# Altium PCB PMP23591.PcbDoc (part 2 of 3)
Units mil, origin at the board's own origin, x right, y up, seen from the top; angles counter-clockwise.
Board outline 3937.01 x 3937.01 mil, 6 copper layers (Top Layer, GND, Power Layer, Signal Layer, GND (Mid4), Bottom Layer), stack 66.824 mil thick; 197 components, 79 nets, 496 pads, 588 vias.
Unrouted connection lines stored in the file: 309.
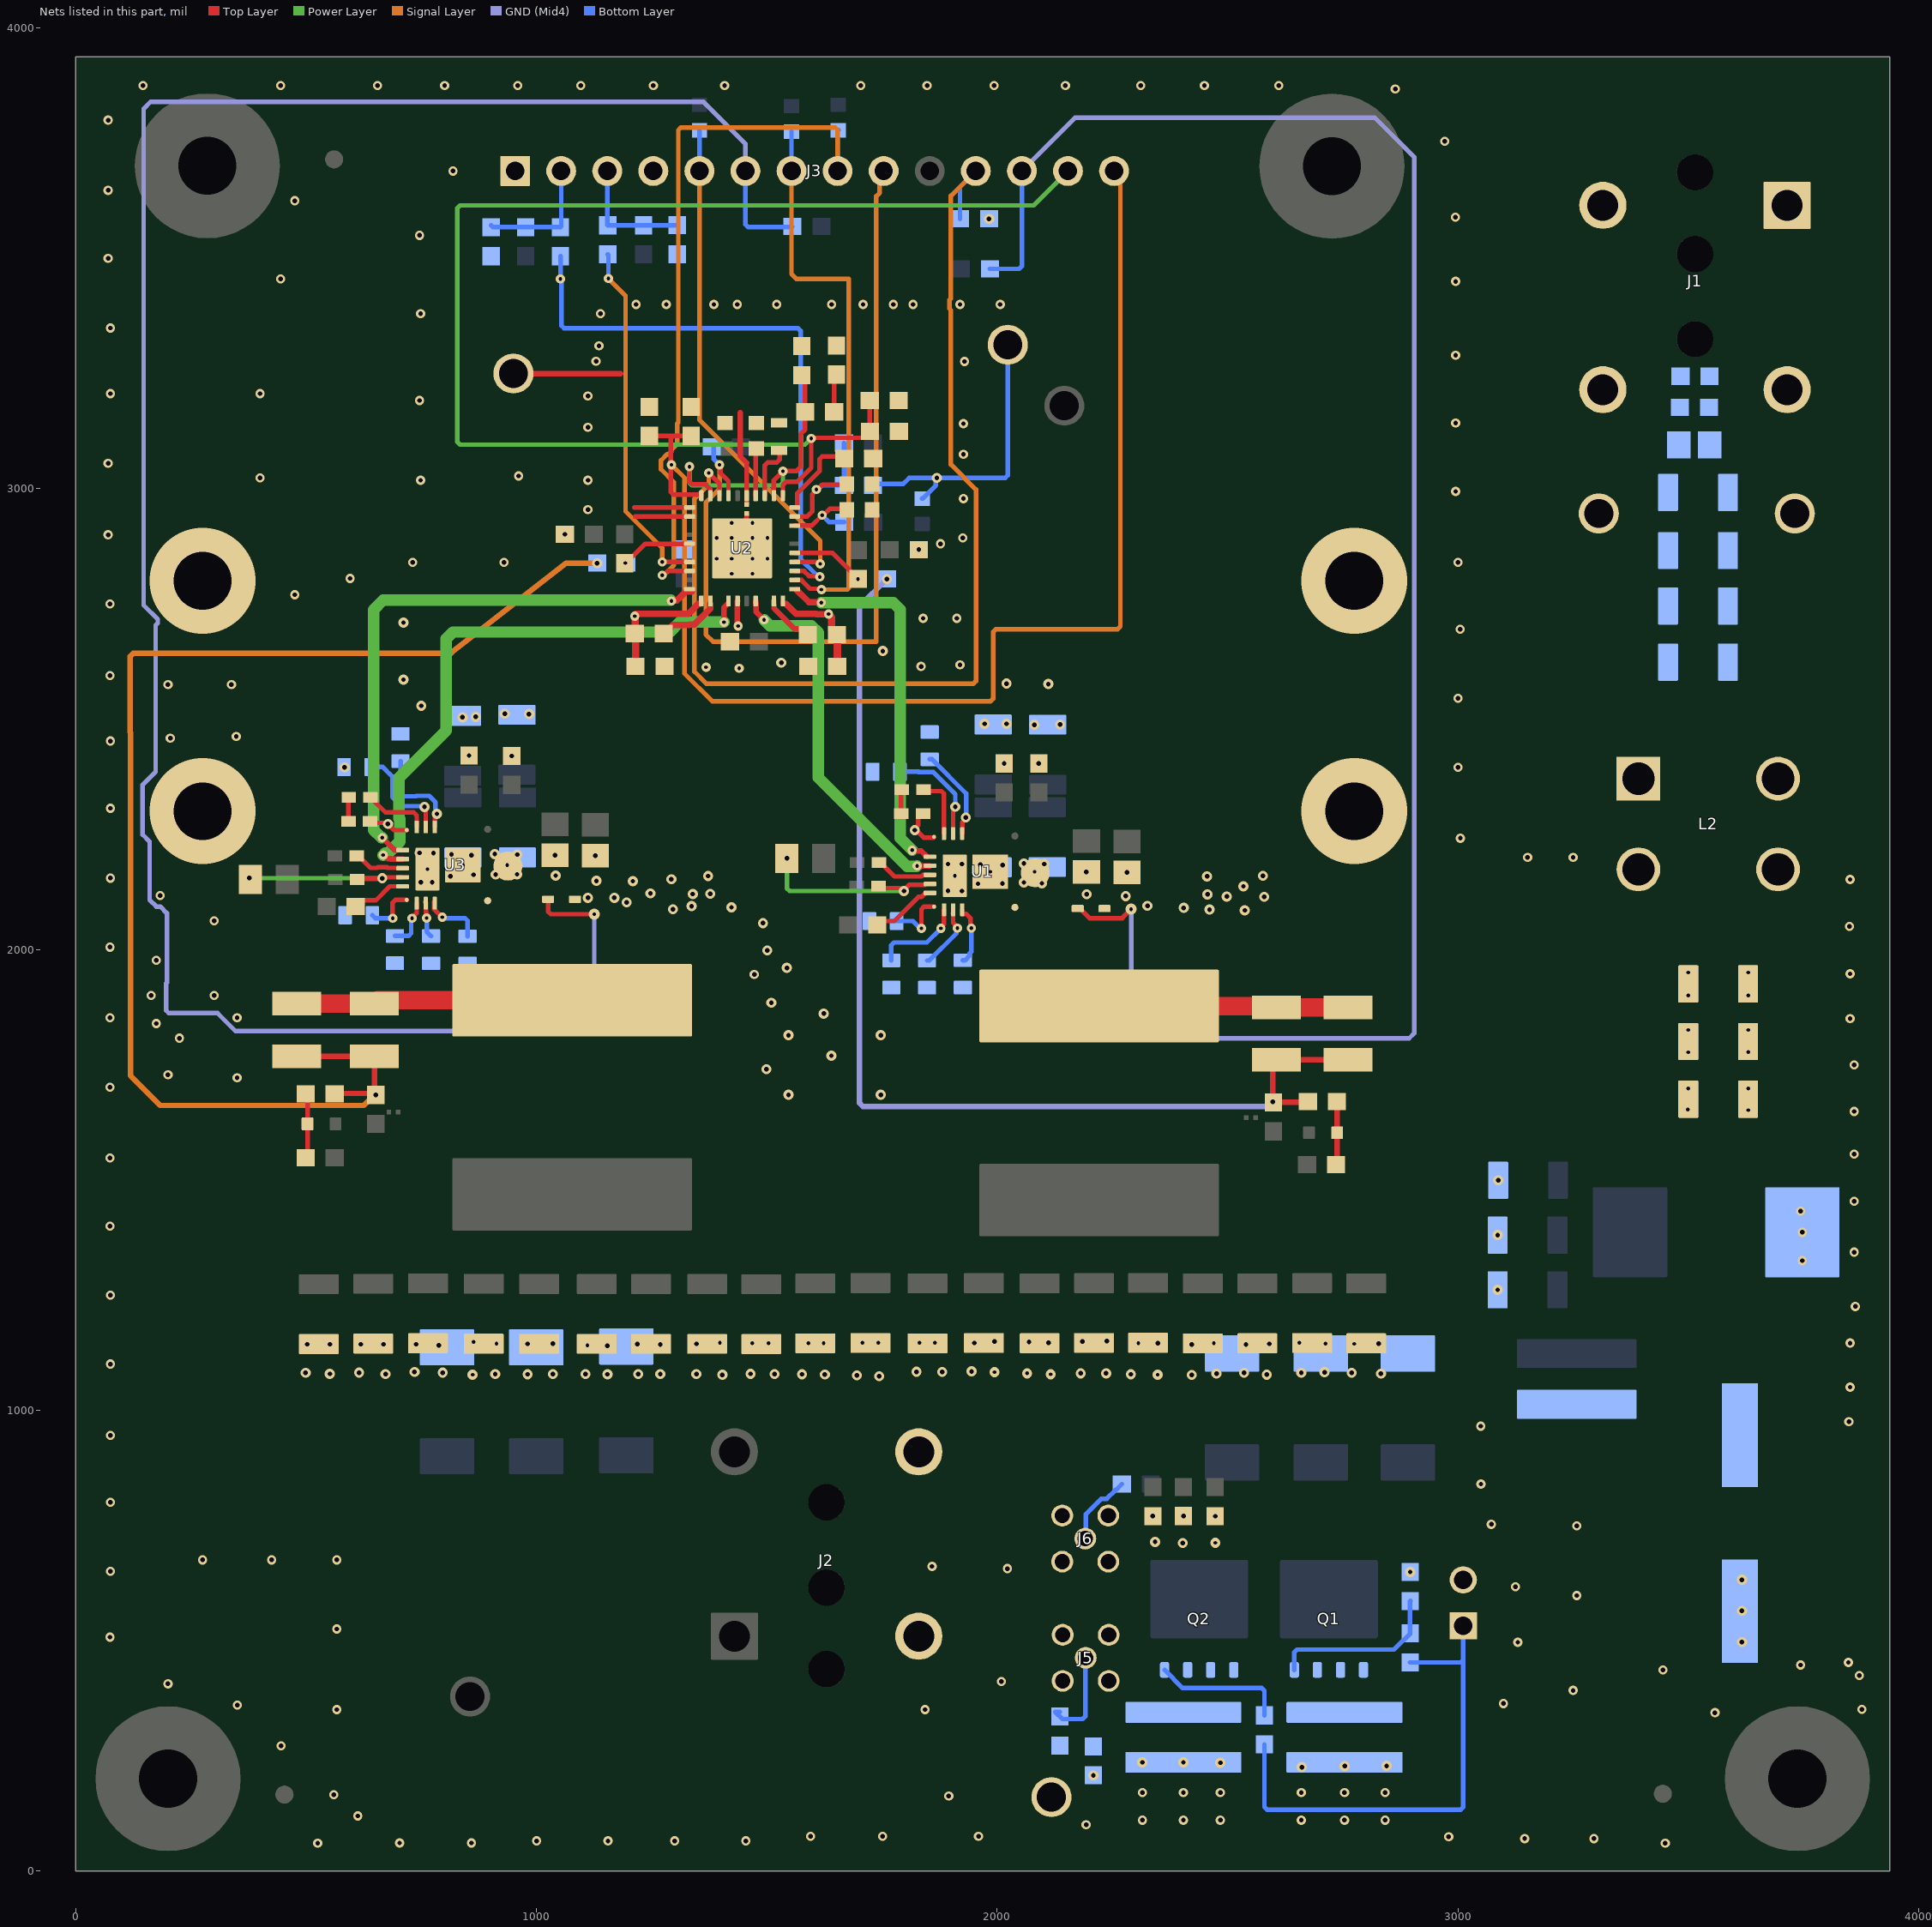
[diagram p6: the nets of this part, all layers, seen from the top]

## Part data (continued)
C2 C57: library part CMP-0007081-4, "CAP, CERM, 1000 pF, 100 V, +/- 10%, X7R, AEC-Q200 Grade 1, 0603", Cap_Case=0603, Manufacturer=TDK, Supplier Part Number 1=445-5806-1-ND, TempCo=X7R, Tolerance_%=10%, Value1="1.97137 ohm", Value2=100V, ValueDisplayed=1000pF
C3 C58: library part CMP-0007468-5, "CAP, CERM, 0.01 uF, 100 V, +/- 10%, X7R, 0603", Cap_Case=0603, Manufacturer=MuRata, Supplier Part Number 1=GRM188R72A103KA01D-ND, TempCo=X7R, Tolerance_%=10%, Value1=Unknown, Value2=100V, ValueDisplayed=0.01uF
C4: library part CMP-0007722-2, "CAP, CERM, 0.1 uF, 100 V, +/- 10%, X7R, 0805", Cap_Case=0805, Manufacturer=Kemet, Supplier Part Number 1=399-3486-1-ND, TempCo=X7R, Tolerance_%=10%, Value1="0.064 ohm", Value2=100V, ValueDisplayed=0.1uF
C5 C6 C7 C8 C9 C10 C11 C12 C13 C14 C15 C16 C17 C18 C19 C20 C21 C45 C46 C47 C48: library part CMP-0093675-1, "4.7uF ±10% 100V Ceramic Capacitor X7S 1210 (3225 Metric)", Manufacturer=Murata, Operating Temperature Range="-55°C to +125°C", TempCo=22%, Temperature Characteristic=X7S, Tolerance_%=10%, ValueDisplayed=4.7uF
C22 C53: library part CMP-0008013-2, "CAP, CERM, 4.7 uF, 25 V, +/- 10%, X7S, AEC-Q200 Grade 1, 0805", Cap_Case=0805, Manufacturer=MuRata, Supplier Part Number 1=81-GCM21BC71E475KE6L, TempCo=X7S, Tolerance_%=10%, Value1=Unknown, Value2=25V, ValueDisplayed=4.7uF
C23 C28 C54 C56: library part CMP-0080702-1, "CAP, CERM, 0.1 µF, 16 V,+/- 5%, X7R, AEC-Q200 Grade 1, 0402", Cap_Case=0402, Manufacturer=MuRata, Supplier Part Number 1=490-16433-1-ND, TempCo=X7R, Tolerance_%=5%, Value2=16V, ValueDisplayed=0.1µF
C24 C25 C38 C42 C44 C49 C50 C55 C59 C75 C77 C78: library part CMP-0007077-5, "CAP, CERM, 0.1 uF, 25 V, +/- 10%, X7R, AEC-Q200 Grade 1, 0603", Cap_Case=0603, Manufacturer=TDK, Supplier Part Number 1=445-5667-1-ND, TempCo=X7R, Tolerance_%=10%, Value1=Unknown, Value2=25V, ValueDisplayed=0.1uF
C26 C27 C51 C52: library part CMP-0007996-2, "CAP, CERM, 0.22 uF, 100 V, +/- 10%, X7R, 0805", Cap_Case=0805, Manufacturer="Samsung Electro-Mechanics", TempCo=X7R, Tolerance_%=10%, Value1=Unknown, Value2=100V, ValueDisplayed=0.22uF
C29 C30 C31 C32 C33 C60 C61 C62 C63 C64 C72 C73 C74 C76 C79 C80 C81 C82 C83 C84: library part CMP-0036912-1, "Cap Ceramic 22uF 25V X7R 20% Pad SMD 1210 +125°C Automotive T/R", Manufacturer=TDK, Operating Temperature Range="-55°C to +125°C", TempCo=15%, Temperature Characteristic=X7R, Tolerance_%=0.2%, ValueDisplayed=22uF
C34: library part CMP-0092618-1, "Cap Tant Polymer 220uF 16VDC E CASE 20% (7.3 X 4.3 X 4.1mm) SMD 7343-43 0.025 Ohm 125C T/R", Digikey Part Number=478-TCME227M016R0025ECT-ND, Leakage Current=352uA, Manufacturer=AVX, Mouser Part Number=581-TCME227M016R025E, Operating Temperature Range="-55°C to +125°C", Tolerance_%=20%, ValueDisplayed=220uF
C35 C36 C65 C66 C67: library part CMP-0124500-1, "Cap Tant Polymer 150uF 16VDC E CASE 20%( 7.3 X 4.3 X 4.1mm) J Lead SMD 7343-43 0.025 Ohm 125C T/R", Digikey Part Number=478-TCQE157M016R0025ECT-ND, Leakage Current=240uA, Manufacturer="KYOCERA AVX", Mouser Part Number=581-TCQE157M016R25E, Operating Temperature Range="-55°C to +125°C", Tolerance_%=20%, ValueDisplayed=150uF
C37 C68: library part CMP-0007508-5, "CAP, CERM, 1 uF, 50 V, +/- 10%, X7R, 0603", Cap_Case=0603, Manufacturer="Taiyo Yuden", Supplier Part Number 1=587-3247-1-ND, TempCo=X7R, Tolerance_%=10%, Value1=Unknown, Value2=50V, ValueDisplayed=1uF
C39: library part CMP-0007469-4, "CAP, CERM, 0.1 uF, 100 V, +/- 10%, X7R, 0603", Cap_Case=0603, Manufacturer=MuRata, Supplier Part Number 1=490-3285-1-ND, TempCo=X7R, Tolerance_%=10%, Value1=Unknown, Value2=100V, ValueDisplayed=0.1uF
C40: library part CMP-0064936-4, "CAP, CERM, 4.7 uF, 16 V,+/- 10%, X7R, 0603", Cap_Case=0603, Manufacturer=MuRata, TempCo=X7R, Tolerance_%=10%, Value1=Unknown, Value2=16V, ValueDisplayed=4.7uF
C41: library part CMP-0079154-1, "CAP, CERM, 1 µF, 16 V,+/- 10%, X7R, AEC-Q200 Grade 1, 0603", Cap_Case=0603, Manufacturer=MuRata, Supplier Part Number 1=490-12657-1-ND, TempCo=X7R, Tolerance_%=10%, Value2=16V, ValueDisplayed=1µF
C43 C69: library part CMP-0007130-4, "CAP, CERM, 100 pF, 100 V, +/- 5%, C0G/NP0, AEC-Q200 Grade 1, 0603", Cap_Case=0603, Manufacturer=MuRata, Supplier Part Number 1=490-4771-1-ND, TempCo=C0G/NP0, Tolerance_%=5%, Value1=Unknown, Value2=100V, ValueDisplayed=100pF
C70: library part CMP-0007069-4, "CAP, CERM, 10 pF, 50 V, +/- 5%, C0G/NP0, AEC-Q200 Grade 1, 0603", Cap_Case=0603, Manufacturer=TDK, Supplier Part Number 1=445-5628-1-ND, TempCo=C0G/NP0, Tolerance_%=5%, Value1=Unknown, Value2=50V, ValueDisplayed=10pF
C71: library part CMP-0007143-4, "CAP, CERM, 0.01 uF, 50 V, +/- 10%, X7R, AEC-Q200 Grade 1, 0603", Cap_Case=0603, Manufacturer=MuRata, Supplier Part Number 1=490-4778-1-ND, TempCo=X7R, Tolerance_%=10%, Value1=Unknown, Value2=50V, ValueDisplayed=0.01uF
"CAUTION HOT SURFACE1": library part CMP-0074837-2, "IEC 61010-1 Hot Surface Warning", Manufacturer="Texas Instruments"
FID1 FID2 FID3: library part CMP-0077181-1, "Fiducial mark.  There is nothing to buy or mount.", Manufacturer=N/A
GND1 PGND1: library part CMP-0055148-1, "Test Point, Multipurpose, Black, TH", Color=Black, Manufacturer=Keystone, PartNumber=5011, Supplier Part Number 1=36-5011-ND
H1 H2 H3 H4: library part CMP-0003617-1, "Machine Screw, Round, #4-40 x 1/4, Nylon, Philips panhead", Manufacturer="B&F Fastener Supply", Supplier Part Number 1=H542-ND
H5 H6 H7 H8: library part CMP-0003610-1, "Standoff, Hex, 0.5\"L #4-40 Nylon", Manufacturer=Keystone, Supplier Part Number 1=36-1902C-ND
J1 J2: library part CMP-0077513-2, "Terminal Block, 10.16mm, 2x1, Tin, R/A, TH", Color=Green, Current_A=65A, Manufacturer=Eaton, Supplier Part Number 1=283-4339-ND, Voltage_V=300V
J3: library part CMP-0075428-1, "Header, 100mil, 14x1, Gold, TH", Color=Black, Current_A=6.3A, Manufacturer=Samtec, Supplier Part Number 1=SAM1029-14-ND, Voltage_V=550V
J4: library part CMP-0054947-1, "Header, 100mil, 2x1, Gold, TH", Manufacturer="TE Connectivity"
J5 J6: library part CMP-0075554-1, "Connector, MMCX 50 ohm, TH", Manufacturer=Samtec, Supplier Part Number 1=88K0549
L1: library part CMP-0086238-1, "Inductor, 1 µH, 30 A, 0.00276 ohm, AEC-Q200 Grade 0, SMD", Manufacturer=Cyntec, Value1="0.00276 ohm", Value2=30A, ValueDisplayed=1µH
L2: library part CMP-0084205-1, "Coupled inductor, 16 µH, 0.0027 ohm, TH", Manufacturer="Wurth Elektronik", ValueDisplayed=16µH
L4: library part CMP-0047844-1, "Power Choke Coil 2.5uH 20% 100kHz 2.53mOhm 32A AECQ200 13.3x12.8x8.0mm SMT", Manufacturer=CYNTEC, Operating Temperature Range="-55°C to +180°C", Test Frequency=100kHz, Tolerance_%=20%
L6: library part CMP-0047844-1, "Power Choke Coil 2.5uH 20% 100kHz 2.53mOhm 32A AECQ200 13.3x12.8x8.0mm SMT", Manufacturer=CYNTEC, Operating Temperature Range="-55°C to +180°C", Part Number=VCUD128T-2R5MS8, Test Frequency=100kHz, Tolerance_%=20%
LBL1: library part CMP-0003625-1, "Thermal Transfer Printable Labels, 0.650\" W x 0.200\" H - 10,000 per roll", Manufacturer=Brady, Supplier Part Number 1=97C5133
Logo1: library part CMP-0074844-1
Logo2: library part CMP-0074838-1, "Texas Instrument Corporate Signature"
Logo3: library part CMP-0074847-1, "FCC_disclaimer"
Logo4: library part CMP-0074769-1
NT1 NT2 NT3: library part CMP-0078142-6, "Single point connection between nets.", Manufacturer=N/A
Q1 Q2: library part CMP-0000584-2, "MOSFET, N-CH, 30 V, 51 A, DNK0008A (VSON-CLIP-8)", Alternate Manufacturer=None, Manufacturer="Texas Instruments", Value1=0.007, Value2="97 nC"
R1: library part CMP-0084352-2, "1 Ohms ±1% 2W Chip Resistor Wide 2512 (6432 Metric), 1225 Automotive AEC-Q200 Thick Film", Digikey Part Number=RCL1.00ECT-ND, Manufacturer="Vishay Dale", Mouser Part Number=71-RCL12251R00FKEG, Operating Temperature Range="-55°C to +155°C", Power_W=2W, TempCo=100ppm/°C, Tolerance_%=1%
R2 R3 R21 R26: library part CMP-0026898-3, "RES, 2.2, 5%, 0.063 W, AEC-Q200 Grade 0, 0402", Manufacturer=Vishay-Dale, Power_W=63mW, Supplier Part Number 1=541-2.2JCT-ND, TempCo="200 ppm/C", Tolerance_%=5%, Value2=0.063W, Value_Code=2R20, ValueDisplayed=2.2
R4 R27 R62 R63: library part CMP-0083024-1, "RES, 2.49 k, 1%, 0.5 W, 1210", Manufacturer=Yageo, Power_W=500mW, TempCo="100 ppm/C", Tolerance_%=1%, Value2=0.5W, Value_Code=2k49, ValueDisplayed=2.49k
R5 R6 R7 R8 R11 R14 R29 R30 R31 R32 R34 R38: library part CMP-0122893-1, "RES Thick Film, 0Ω, , 0.33W, , 0603", Manufacturer=Vishay, Operating Temperature Range="-55°C to +155°C", Power=250mW, Power_W=330mW
R9 R33: library part CMP-0095715-1, "NTC Thermistor for Temperature Sensor, Automotive, 0603, 47kΩ, 5%, 0.046mA, 5V", B Tolerance=1%, Digikey Part Number=490-NCU18WB473D60RBTR-ND, Manufacturer=Murata, Max Current=0.046mA, Mouser Part Number=81-NCU18WB473D60RB, Operating Temperature Range="-40°C to +150℃", Tolerance_%=5%
R10 R20: library part CMP-0025697-4, "RES, 0, 5%, 0.1 W, AEC-Q200 Grade 0, 0603", Manufacturer=Vishay-Dale, Power_W=100mW, Supplier Part Number 1=541-0.0GCT-ND, TempCo="200 ppm/C", Tolerance_%=5%, Value2=0.1W, Value_Code=0000, ValueDisplayed=0
R12 R35: library part CMP-0022268-4, "RES, 2.00 k, 1%, 0.1 W, AEC-Q200 Grade 0, 0603", Manufacturer=Vishay-Dale, Power_W=100mW, Supplier Part Number 1=541-2.00KHCT-ND, TempCo="100 ppm/C", Tolerance_%=1%, Value2=0.1W, Value_Code=2k00, ValueDisplayed=2.00k
R13 R36: library part CMP-0081973-1, "RES, 0, 0%, 0.25 W, AEC-Q200 Grade 0, 0603", Manufacturer=Vishay-Dale, Power_W=250mW, Supplier Part Number 1=541-2779-1-ND, Tolerance_%=0%, Value2=0.25W, Value_Code=0
R15 R39: library part CMP-0025817-4, "RES, 4.7 k, 5%, 0.1 W, AEC-Q200 Grade 0, 0603", Manufacturer=Vishay-Dale, Power_W=100mW, Supplier Part Number 1=541-4.7KGCT-ND, TempCo="200 ppm/C", Tolerance_%=5%, Value2=0.1W, Value_Code=4k70, ValueDisplayed=4.7k
R16 R19 R25 R28 R48 R50 R51 R54 R61 R64 R65: library part CMP-0021998-4, "RES, 10.0 k, 1%, 0.1 W, AEC-Q200 Grade 0, 0603", Manufacturer=Vishay-Dale, Power_W=100mW, Supplier Part Number 1=541-10.0KHCT-ND, TempCo="100 ppm/C", Tolerance_%=1%, Value2=0.1W, Value_Code=10k0, ValueDisplayed=10.0k
R17 R44: library part CMP-0022707-2, "RES, 49.9, 1%, 0.1 W, AEC-Q200 Grade 0, 0603", Manufacturer=Panasonic, Power_W=100mW, Supplier Part Number 1=P49.9HCT-ND, TempCo="100 ppm/C", Tolerance_%=1%, Value2=0.1W, Value_Code=49R9, ValueDisplayed=49.9
R18 R45: library part CMP-0079245-1, "RES, 140 k, 0.1%, 0.1 W, AEC-Q200 Grade 0, 0603", Manufacturer=Panasonic, Power_W=100mW, Supplier Part Number 1=P140KDBCT-ND, TempCo="25 ppm/C", Tolerance_%=0.1%, Value2=0.1W, Value_Code=140k
R22: library part CMP-0022414-4, "RES, 41.2 k, 1%, 0.1 W, AEC-Q200 Grade 0, 0603", Manufacturer=Vishay-Dale, Power_W=100mW, Supplier Part Number 1=541-41.2KHCT-ND, TempCo="100 ppm/C", Tolerance_%=1%, Value2=0.1W, Value_Code=41k2, ValueDisplayed=41.2k
R23: library part CMP-0022204-4, "RES, 20.0 k, 1%, 0.1 W, AEC-Q200 Grade 0, 0603", Manufacturer=Vishay-Dale, Power_W=100mW, Supplier Part Number 1=541-20.0KHCT-ND, TempCo="100 ppm/C", Tolerance_%=1%, Value2=0.1W, Value_Code=20k0, ValueDisplayed=20.0k
R24: library part CMP-0022486-4, "RES, 52.3 k, 1%, 0.1 W, AEC-Q200 Grade 0, 0603", Manufacturer=Vishay-Dale, Power_W=100mW, Supplier Part Number 1=541-52.3KHCT-ND, TempCo="100 ppm/C", Tolerance_%=1%, Value2=0.1W, Value_Code=52k3, ValueDisplayed=52.3k
R37 R55 R56: library part CMP-0022448-4, "RES, 49.9, 1%, 0.1 W, AEC-Q200 Grade 0, 0603", Manufacturer=Vishay-Dale, Power_W=100mW, Supplier Part Number 1=541-49.9HCT-ND, TempCo="100 ppm/C", Tolerance_%=1%, Value2=0.1W, Value_Code=49R9, ValueDisplayed=49.9
R40 R60: library part CMP-0022101-4, "RES, 191 k, 1%, 0.1 W, AEC-Q200 Grade 0, 0603", Manufacturer=Vishay-Dale, Power_W=100mW, Supplier Part Number 1=541-191KHCT-ND, TempCo="100 ppm/C", Tolerance_%=1%, Value2=0.1W, Value_Code=191k
R41 R42 R43: library part CMP-0021990-4, "RES, 100 k, 1%, 0.1 W, AEC-Q200 Grade 0, 0603", Manufacturer=Vishay-Dale, Power_W=100mW, Supplier Part Number 1=541-100KHCT-ND, TempCo="100 ppm/C", Tolerance_%=1%, Value2=0.1W, Value_Code=100k
R46: library part CMP-0022443-4, "RES, 48.7 k, 1%, 0.1 W, AEC-Q200 Grade 0, 0603", Manufacturer=Vishay-Dale, Power_W=100mW, Supplier Part Number 1=541-48.7KHCT-ND, TempCo="100 ppm/C", Tolerance_%=1%, Value2=0.1W, Value_Code=48k7, ValueDisplayed=48.7k
R47 R59: library part CMP-0022458-4, "RES, 4.99 k, 1%, 0.1 W, AEC-Q200 Grade 0, 0603", Manufacturer=Vishay-Dale, Power_W=100mW, Supplier Part Number 1=541-4.99KHCT-ND, TempCo="100 ppm/C", Tolerance_%=1%, Value2=0.1W, Value_Code=4k99, ValueDisplayed=4.99k
R49: library part CMP-0022364-4, "RES, 38.3 k, 1%, 0.1 W, AEC-Q200 Grade 0, 0603", Manufacturer=Vishay-Dale, Power_W=100mW, Supplier Part Number 1=541-38.3KHCT-ND, TempCo="100 ppm/C", Tolerance_%=1%, Value2=0.1W, Value_Code=38k3, ValueDisplayed=38.3k
R52 R53: library part CMP-0025743-4, "RES, 1.0, 5%, 0.1 W, AEC-Q200 Grade 0, 0603", Manufacturer=Vishay-Dale, Power_W=100mW, Supplier Part Number 1=541-1.0GCT-ND, TempCo="200 ppm/C", Tolerance_%=5%, Value2=0.1W, Value_Code=1R00, ValueDisplayed=1.0
R57 R58: library part CMP-0124591-1, "200 mOhms ±1% 1.5W Chip Resistor Wide 2512 (6432 Metric), 1225 Automotive AEC-Q200, Moisture Resistant Thick Film", Digikey Part Number=2019-WK73S3ATTER200FCT-ND, Manufacturer="KOA Speer", Mouser Part Number=660-WK73S3ATTER200F, Operating Temperature Range="-55°C to +155°C", Power_W=1.5W, TempCo=200ppm/°C, Tolerance_%=1%
RT1 RT2: library part CMP-0123120-1, "Automotive ±1% tolerance 10kΩ linear thermistor available in an 0402 package option 2-SOT-5X3 -40 to 150", Digikey Part Number=296-TMP6131QDYARQ1CT-ND, Manufacturer="Texas Instruments", Max Current=400uA, Mouser Part Number=595-TMP6131QDYARQ1, Operating Temperature Range="-40°C to +150°C", TempCo=6400ppm/°C, Tolerance_%=1%
U1 U3: library part CMP-0121493-2, "100-V, 53-A GaN Half-Bridge Power Stage", Manufacturer="Texas Instruments", Max Supply Voltage=5.25V, Min Supply Voltage=4.75V, Nominal Supply Current=12mA, Operating Temperature Range="-40°C to +150°C"
U2: library part CMP-0122321-1, "Automotive, 4-V to 80-V, Functional Safety-Compliant, Dual Synchronous Buck Controller With Low IQ", Manufacturer="Texas Instruments", Max Supply Voltage=80V, Min Supply Voltage=4V, Nominal Supply Current=130uA, Operating Temperature Range="-40°C to +150°C", Output Voltage=0.8-60V, Switching Frequency=100-2200kHz
VIN1 VOUT_BODE VOUT_PWR1: library part CMP-0055147-1, "Test Point, Multipurpose, Red, TH", Color=Red, Manufacturer=Keystone, PartNumber=5010, Supplier Part Number 1=36-5010-ND
ZZ1: library part CMP-0003616-3
ZZ2: library part CMP-0077236-1
ZZ3: library part CMP-0077237-1
ZZ4: library part CMP-0077238-1

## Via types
v1: diameter 22, hole 10, Top Layer to Bottom Layer, tented both sides, 256 vias
v2: diameter 20, hole 10, Top Layer to Bottom Layer, tented both sides, 193 vias
v3: diameter 22, hole 8, Top Layer to Bottom Layer, tented both sides, 59 vias
v4: diameter 20, hole 8, Top Layer to Bottom Layer, tented both sides, 56 vias
v5: diameter 19.68, hole 7.87, Top Layer to Bottom Layer, tented both sides, 18 vias
v6: diameter 230, hole 125, Top Layer to Bottom Layer, 4 vias
v7: diameter 24, hole 8, Top Layer to Bottom Layer, tented both sides, 2 vias

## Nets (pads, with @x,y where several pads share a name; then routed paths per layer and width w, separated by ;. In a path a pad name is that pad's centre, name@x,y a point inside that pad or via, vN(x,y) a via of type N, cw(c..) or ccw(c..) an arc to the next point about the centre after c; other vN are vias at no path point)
+Filter: C12.2 C13.2 C14.2 C15.2 C16.2 C17.2 L1.1 L2.3
  other v2: 3747.72,1324.51 3747.72,1386.05 3743.74,1431.94
  other v4: 3630.52,1651.11 3630.52,1697.86 3630.52,1777.14 3630.52,1825 3630.52,1900 3630.52,1950
+Vin_Main: C2.1 C3.2 C4.1 C5.2 C6.2 C7.2 C8.2 J1.1 L2.4 VIN1.1
AGND: AGND_CTRL1.1 C41.1 C42.1 C55.1 C70.2 C71.2 NT3.2 R16.2 R19.2 R22.1 R23.1 R24.1 R25.2 R48.2 U2.1 U2.2 U2.31 | length 675.3
  Top Layer w10: 1212.54,2959.3 1331.96,2959.3 U2.1@1332.04,2959.22 ; 1213.6,2939.62 1213.69,2939.53 U2.2@1332.04,2939.53 ; NT3.2@1456.05,2966.02 1456.05,3056.23
  Top Layer w12: AGND_CTRL1.1@949.94,3250 1182.35,3250 ; 1442.17,3165.14 1442.17,3070.12 1456.05,3056.23
AGND2: C22.2 C23.2 R5.1 R6.1 R7.1 R8.1 U1.15 | length 436.1
  Top Layer w10: C23.2@1742.48,2137.45 1746.64,2133.29 1787.6,2133.29 1794.15,2126.75 v1(1797.4,2126.75) 1797.4,2128.65 1809.25,2140.5 1842.82,2140.5 1844.44,2142.12 U1.15@1845.27,2142.12
  Power Layer w10: v1(1543.46,2197.61) 1543.46,2132.6 1549.31,2126.75 v1(1797.4,2126.75)
AGND3: C53.2 C54.2 R29.1 R30.1 R31.1 R32.1 U3.15 | length 389.4
  Top Layer w10: C54.2@610.6,2151.79 611.89,2153.08 663.81,2153.08 v1(665.1,2154.38) 667.33,2156.61 U3.15@709.37,2156.61
  Power Layer w10: v1(376.72,2154.87) 376.97,2154.62 664.85,2154.62 v1(665.1,2154.38)
Bode: BODE.1 R37.1 R45.2 | length 643.6
  Bottom Layer w10: R45.2@1730.43,3007.42 1733.12,3010.1 1795.65,3010.1 1809.05,3023.49 v1(1868.99,3023.49) ; R37.1@1836.84,2978.51 1837.82,2978.51 1866.69,3007.38 1866.69,3021.2 v1(1868.99,3023.49) ; BODE.1@2023.01,3312.4 2023.01,3029.35 2017.15,3023.49 v1(1868.99,3023.49)
COMP: C70.1 R49.2 U2.28 U2.35 | length 675.9
  Top Layer w10: v4(1332.04,3047.92) 1331.96,3047.84 1331.96,3015.35 1337.82,3009.49 1366.73,3009.49 1377.23,2998.99 1377.23,2984.89 U2.35@1377.31,2984.81 ; U2.28@1515.11,2984.81 1515.11,3018.38 v4(1534.79,3038.07) 1563.78,3038.07 1573.34,3047.62 1573.34,3118.53 1583.05,3128.25 R49.2@1583.05,3166.84 1583.05,3239.22 C70.1@1575.88,3246.39
  Power Layer w10: v4(1332.04,3047.92) 1332.04,3013.14 1337.89,3007.28 1528.93,3007.28 1534.79,3013.14 v4(1534.79,3038.07)
EN1: R47.2 U2.20 | length 1288.5
  Top Layer w10: U2.20@1560.38,2821.42 1560.46,2821.34 1580.61,2821.34 1591.3,2810.65 1613.08,2810.65 v4(1614.99,2808.74)
  Bottom Layer w10: R47.2@1051.93,3504.77 v4(1051.93,3455.2) 1053.84,3453.29 1053.84,3354.2 1059.7,3348.35 1567.48,3348.35 1573.34,3342.49 1573.34,2847.02 1606.3,2814.06 1606.96,2814.06 1612.29,2808.74 v4(1614.99,2808.74)
EN2: R59.2 U2.6 | length 775.7
  Top Layer w10: v4(1272.77,2841.11) U2.6@1332.04,2841.11
  Signal Layer w10: v4(1156.1,3456.14) 1193.29,3418.95 1193.29,2950.85 1272.77,2871.36 v4(1272.77,2841.11)
  Bottom Layer w10: R59.2@1154.68,3508.66 1156.1,3507.24 v4(1156.1,3456.14)
FB: R45.1 R46.1 R48.1 U2.25 | length 320.1
  Top Layer w10: U2.25@1560.38,2939.53 1587.19,2939.53 1598.35,2950.69 1598.35,2987.4 1607.27,2996.32 v4(1607.27,2998.26) 1609.98,2998.26 1620.41,3008.69 1672.39,3008.69 R48.1@1673.37,3009.67
  Bottom Layer w10: v4(1607.27,2998.26) 1609.98,2998.26 1619.14,3007.42 R45.1@1667.44,3007.42 R46.1@1667.44,3098.93
GNDin: C2.2 C3.1 C4.2 C5.1 C6.1 C7.1 C8.1 GND1.1 J1.2 L2.1
HO1: U1.12 U2.18 | length 812.7
  Top Layer w12: v4(1815.19,2215.35) 1816.72,2213.82 1834.71,2213.82 U1.12@1847.35,2201.17
  Top Layer w14: U2.18@1565.19,2779.97 1591.54,2753.63 1616.98,2753.63 v4(1618.12,2752.48)
  Power Layer w25: v4(1618.12,2752.48) 1774.4,2752.48 1789.05,2737.84 1789.05,2241.49 v4(1815.19,2215.35)
HO2: U2.9 U3.12 | length 1251.9
  Top Layer w12: v4(665.02,2242.42) 691.59,2215.85 U3.12@696.1,2215.85
  Top Layer w14: v4(1292.87,2756.46) 1294.02,2757.61 1304.86,2757.61 1324.28,2777.02 1336.67,2777.02
  Power Layer w25: v4(665.02,2242.42) 663.12,2242.42 646.09,2259.45 646.09,2736.85 667.13,2757.89 v4@1291.44,2757.89
HS1: R3.1 R11.1 R14.1 U1.11 | length 93.5
  Top Layer w10: R3.1@1839.03,2294.46 1835.09,2294.46 1828.28,2287.64 1828.28,2269.26 1821.15,2262.13 v1(1821.15,2258.88) 1824.4,2258.88 1840.87,2242.41 U1.11@1862.49,2242.41
HS2: R26.1 R34.1 R38.1 U3.11 | length 87.3
  Top Layer w10: R26.1@638.89,2278.23 642.38,2274.74 675.17,2274.74 690.94,2258.97 U3.11@718.23,2258.97
  other v1: 677.46,2272.44 583.37,2395.23
IMON1: C42.2 J3.13 R16.1 U2.27 | length 3000.2
  Top Layer w10: U2.27@1534.79,2984.81 1534.79,3008.1 1541.88,3015.19 1566.19,3015.19 1596.21,3045.22 v4(1596.21,3109.06) 1597.74,3110.59 1708.82,3110.59 C42.2@1718.17,3119.94 ; R16.1@1723.35,3191.69 1723.51,3191.53 C42.2@1723.51,3124.29
  Power Layer w10: v4(1596.21,3109.06) 1582.68,3095.52 834.09,3095.52 828.23,3101.38 828.23,3609.14 834.09,3615 2078.94,3615 J3.13@2153.51,3689.57
IMON2: C55.2 J3.14 R25.1 U2.36 | length 2869.3
  Top Layer w10: R25.1@1244.86,3114.68 1297.2,3114.68 ; C55.2@1335.42,3114.68 1335.31,3114.79 1297.31,3114.79 1297.2,3114.68 ; U2.36@1357.63,2984.81 1357.63,2986.88 1357.55,2986.96 1297.31,2986.96 1291.45,2992.82 1291.45,3050.42 v4(1292.87,3051.84) 1291.45,3053.25 1291.45,3108.93 1297.2,3114.68
  Signal Layer w10: v4(1292.87,3051.84) 1321.16,3023.54 1321.16,2599 1381.79,2538.37 1985.26,2538.37 1991.12,2544.23 1991.12,2689.14 1996.97,2695 2261.49,2695 2267.35,2700.86 2267.35,3660.87 2253.51,3674.7 J3.14@2253.51,3689.57
ISNS1+: C43.2 R17.1 U2.22 | length 175.5
  Top Layer w10: U2.22@1560.38,2860.79 1642.21,2860.79 1697.58,2805.42 v4(1697.58,2803.92) ; C43.2@1698.02,2803.92 C43.2@1698.06,2803.96
  Bottom Layer w10: R17.1@1701.42,2803.92 R17.1@1711.21,2794.13
ISNS2+: C69.2 R44.1 U2.4 | length 163.6
  Top Layer w10: C69.2@1191.39,2838.16 1192.54,2837.01 1192.54,2840.29 1205.09,2852.84 1208.37,2852.84 1236,2880.48 U2.4@1332.04,2880.48
  Bottom Layer w10: R44.1@1190.71,2838.42 R44.1@1192.54,2836.59
  other v4: 1192.54,2838.65
LO1: U1.13 U2.15 | length 815.7
  Top Layer w12: U2.15@1475.74,2756.46 1475.74,2751.73 1476.82,2750.65 1476.82,2732.62 v4(1493.96,2715.48) ; v4(1825.94,2181.25) 1825.99,2181.3 1853.86,2181.3 U1.13@1854.05,2181.49
  Power Layer w25: v4(1493.96,2715.48) 1506.8,2702.64 1596.75,2702.64 1611.39,2687.99 1611.39,2372.65 1804.02,2180.03 1824.73,2180.03 v4(1825.94,2181.25)
LO2: U2.12 U3.13 | length 1238.4
  Top Layer w12: v4(667.17,2204.76) 669.34,2204.76 676.98,2197.12 682.8,2197.12 683.95,2195.98 U3.13@709.37,2195.98 ; v4(1406.84,2710.46) 1406.84,2741.89 U2.12@1415.6,2750.65
  Power Layer w25: v4(667.17,2204.76) 671.95,2209.54 678.64,2209.54 702.84,2233.74 702.84,2282.95 701.72,2284.07 701.72,2373.22 804.08,2475.58 804.08,2674.21 818.73,2688.86 1289.28,2688.86 1310.89,2710.46 v4(1406.84,2710.46)
NetC1_1: C1.1 R1.1
NetC28_1: C28.1 R3.2 | length 51.2
  Top Layer w10: R3.2@1791.38,2292.61 1791.38,2342.76 C28.1@1792.13,2343.5
NetC28_2: C28.2 U1.10 | length 133.9
  Top Layer w10: C28.2@1839.37,2343.5 1878.71,2343.5 1884.56,2337.65 U1.10@1884.56,2251.37
NetC37_2: C37.2 R4.2 R12.2 R17.2 R62.2 | length 2393.7
  Top Layer w12: R12.2@2674.51,1669.46 2673.22,1668.17 C37.2@2599.45,1668.17 v1(2598.07,1669.56) 2598.07,1752.55 R4.2@2605.7,1760.18 R62.2@2761.83,1760.18
  GND (Mid4) w12: v1(1760.58,2803.92) 1701.25,2744.6 1701.25,1666.28 1708.28,1659.25 2587.76,1659.25 v1(2598.07,1669.56)
NetC38_1: C38.1 R10.1 U2.17 | length 215
  Top Layer w10: U2.17@1534.79,2756.46 1534.79,2749.73 1534.87,2749.65 1541.6,2749.65
  Top Layer w14: 1541.6,2749.65 1563.14,2728.11 1607.32,2728.11 1607.82,2727.61 1633.43,2727.61 v4(1633.89,2728.08)
  Top Layer w16: v4(1633.89,2728.08) 1633.89,2726.99 1640.35,2720.54 1640.35,2693.55 C38.1@1650.4,2683.5 ; R10.1@1653.05,2614.89 1653.05,2663.24
NetC38_2: C38.2 U2.16 | length 118.7
  Top Layer w12: U2.16@1515.11,2756.46 1515.11,2747.84 1515.92,2747.03 1515.92,2740.14 1559.99,2696.06 1575.36,2696.06 1586.85,2684.56 C38.2@1586.85,2676.44
NetC44_1: C44.1 R20.1 U2.10 | length 263.9
  Top Layer w14: v4(1213.34,2723.42) v4@1213.97,2722.79 ; v4@1215.16,2728.25 1329.64,2728.25 1350.97,2749.57 1353.47,2749.57 U2.10@1355.55,2751.65 ; R20.1@1226.32,2614.31 R20.1@1226.41,2614.22
  Top Layer w16: C44.1@1213.97,2686.19 v4@1213.97,2722.79 ; R20.1@1214.91,2614.22 C44.1@1214.91,2690.4
NetC44_2: C44.2 U2.11 | length 125
  Top Layer w14: C44.2@1283,2691 1296.15,2704.15 1331.48,2704.15 1332.2,2704.87 1342.65,2704.87 1377.42,2739.64 U2.11@1377.42,2750.09
NetC56_1: C56.1 R26.2 | length 52.1
  Top Layer w10: R26.2@591.65,2278.23 591.65,2329.09 C56.1@592.49,2329.94
NetC56_2: C56.2 U3.10 | length 141.2
  Top Layer w10: C56.2@639.73,2329.94 672.17,2297.51 733.09,2297.51 739.88,2290.71 U3.10@739.88,2265.86
NetC68_2: C68.2 R27.2 R35.2 R44.2 R63.2 | length 2905.8
  Top Layer w12: R63.2@479.59,1767.91 R27.2@648.17,1767.91 C68.2@648.17,1687.27 ; R35.2@562.56,1687.46 647.98,1687.46 C68.2@648.17,1687.27 ; v1(651.15,1684.29) C68.2@648.17,1687.27
  Signal Layer w12: v1@649.56,1685.88 625.06,1661.38 183.03,1661.38 118.75,1725.66 118.75,2470.46 117.56,2471.65 117.56,2635.89 124.59,2642.92 814.64,2642.92 819.6,2647.88 1063.98,2838.42 v1(1131.66,2838.42)
  Bottom Layer w12: R44.2@1132.9,2841.11 R44.2@1135.6,2838.42
NetC71_1: C71.1 R49.1 | length 78.8
  Top Layer w10: R49.1@1646.04,3166.84 1646.04,3243.87 C71.1@1647.26,3245.09
NetC75_2: C75.2 Q1.1 Q1.2 Q1.3 Q2.1 Q2.2 Q2.3 R55.1 R57.2 R58.2
NetJ3_2: J3.2 R40.1 R47.1 R50.1 | length 274.6
  Bottom Layer w10: R50.1@901.41,3571.66 905.31,3567.76 R40.1@976.22,3567.76 R47.1@1051.93,3567.76 1053.51,3569.34 J3.2@1053.51,3689.57
NetJ3_3: J3.3 R59.1 R60.1 R61.1 | length 269.2
  Bottom Layer w10: J3.3@1153.51,3689.57 1153.51,3572.82 R59.1@1154.68,3571.66 1305.03,3571.66 R61.1@1305.34,3571.97
NetJ4_1: J4.1 R52.2 R53.1 | length 1083.2
  Bottom Layer w10: R53.1@2579.93,274.41 2579.93,138.74 2585.79,132.89 3005.85,132.89 3011.7,138.74 3011.7,458.33 ; R52.2@2896.22,452.47 3005.85,452.47 3011.7,458.33 ; J4.1@3011.7,531.76 3011.7,458.33
NetJ5_1: J5.1 R55.2 | length 219
  Bottom Layer w10: R55.2@2136.15,334.8 R55.2@2141.36,329.59 ; R55.2@2136.15,344.81 2126.15,344.81 R55.2@2141.36,329.59 ; J5.1@2191.17,463.27 2191.17,335.45 2185.32,329.59 R55.2@2141.36,329.59
NetJ6_1: J6.1 R56.1 | length 158.6
  Bottom Layer w10: J6.1@2191.17,721.12 2192.05,722 2192.05,773.61 2226.06,807.62 2237.63,807.62 2256.69,826.69 2257.68,826.69 R56.1@2270.52,839.53
NetL4_1: L4.1 R4.1 R62.1 U1.5 | length 540.7
  Top Layer w40: L4.1@2221.16,1877.22 R4.1@2605.7,1877.22 ; R4.1@2605.7,1874.35 R62.1@2761.83,1874.35
NetL6_1: L6.1 R27.1 R63.1 U3.5 | length 677.7
  Top Layer w12: R27.1@648.17,1882.09 R27.1@655.68,1889.61 ; L6.1@918.19,1847.53 L6.1@960.27,1889.61 ; L6.1@972.48,1901.82 L6.1@960.27,1889.61 ; L6.1@1077.4,1889.61 L6.1@960.27,1889.61
  Top Layer w40: R63.1@479.59,1882.09 R27.1@648.17,1882.09 ; R27.1@655.68,1889.61 L6.1@960.27,1889.61
NetQ1_4: Q1.4 R52.1 R54.2 | length 377.5
  Bottom Layer w10: Q1.4@2644.98,436.25 2644.98,474.56 2650.84,480.41 2861.17,480.41 2881.53,500.78 2882.52,500.78 2896.22,514.48 2896.22,585.37 R54.2@2896.59,585.74
NetQ2_4: Q2.4 R53.2 | length 289
  Bottom Layer w10: Q2.4@2363.28,436.15 2402.58,396.85 2574.14,396.85 2579.99,390.99 2579.99,337.47 R53.2@2579.93,337.41
NetR2_2: R2.2 U1.14 | length 124.7
  Top Layer w10: R2.2@1743.18,2188.44 1747.12,2188.44 1777.18,2158.38 1835.42,2158.38 1838.77,2161.72 1853.97,2161.72 U1.14@1854.05,2161.8
NetR5_2: R5.2 U1.1 | length 131.3
  Top Layer w10: v4(1835.38,2045.86) 1835.38,2087.05 1841.24,2092.91 U1.1@1862.91,2092.91
  Bottom Layer w10: R5.2@1781.72,2061.51 1817.02,2061.51 1832.67,2045.86 v4(1835.38,2045.86)
NetR6_2: R6.2 U1.2 | length 198.8
  Top Layer w10: v4(1877.9,2045.86) 1877.9,2048.56 1884.56,2055.23 U1.2@1884.56,2086.02
  Bottom Layer w10: R6.2@1770.08,1976.27 1770.08,2009.13 1775.94,2014.99 1847.03,2014.99 v4(1877.9,2045.86)
NetR7_2: R7.2 U1.3 | length 143.4
  Top Layer w10: U1.3@1903.8,2077.94 U1.3@1903.88,2077.87 ; U1.3@1904.25,2077.24 1904.25,2058.25 1913.51,2048.98 v4(1913.51,2046.27) ; U1.3@1904.25,2077.94 U1.3@1904.25,2086.02
  Bottom Layer w10: R7.2@1847.63,1976.05 1852.56,1976.05 1911.6,2035.09 1911.6,2044.36 v4(1913.51,2046.27)
NetR8_2: R8.2 U1.4 | length 133.5
  Top Layer w10: U1.4@1923.93,2086.02 1923.93,2077.32 1924.01,2077.24 1932.71,2077.24 1941.8,2068.15 1941.8,2048.19 v4(1943.71,2046.27)
  Bottom Layer w10: R8.2@1925.3,1976.31 1930.22,1976.31 1939.99,1986.07 1939.99,1990.99 1943.71,1994.72 v4(1943.71,2046.27)
NetR9_1: R9.1 R12.1 R13.1 | length 137.5
  Top Layer w12: R13.1@2735.62,1533.06 2737.93,1535.37 R9.1@2737.93,1602.18 2737.93,1669.03 R12.1@2737.5,1669.46
NetR11_2: R11.2 U1.8 | length 200.7
  Top Layer w10: U1.8@1923.93,2251.37 1924.01,2251.45 1924.01,2275.37 1931.77,2283.13 v1(1931.77,2286.38)
  Bottom Layer w10: R11.2@1853.43,2412.73 1858.35,2412.73 1932.7,2338.39 1932.7,2287.3 v1(1931.77,2286.38)
NetR14_2: R14.2 U1.9 | length 227.8
  Top Layer w10: U1.9@1904.25,2251.37 1904.25,2301.71 1908.82,2306.29 v1(1908.82,2309.53)
  Bottom Layer w10: R14.2@1788.65,2385.59 1829.04,2385.59 1829.54,2385.09 1860.71,2385.09 1908.82,2336.98 v1(1908.82,2309.53)
NetR15_1: R15.1 U1.16 | length 128.6
  Top Layer w10: R15.1@1739.07,2061.51 1776.6,2061.51 1829.46,2114.36 1836.36,2114.36 U1.16@1843,2121
NetR18_1: R18.1 R19.1 U2.24 | length 182.8
  Top Layer w10: U2.24@1560.38,2919.85 1597.34,2919.85 v4(1619.98,2942.48) 1622.69,2942.48 1636.47,2956.26 1671.49,2956.26 R19.1@1673.37,2954.38
  Bottom Layer w10: v4(1619.98,2942.48) 1635.08,2927.38 R18.1@1667.7,2927.38
NetR21_2: R21.2 U3.14 | length 100
  Top Layer w10: R21.2@609.59,2203.19 613.53,2203.19 639.79,2176.92 653.88,2176.92 655.21,2178.25 674.99,2178.25 676.31,2176.92 695.71,2176.92 U3.14@697.6,2176.92
NetR22_2: R22.2 U2.26 | length 186.3
  Top Layer w10: U2.26@1560.38,2959.22 1566.21,2959.22 1566.29,2959.3 1566.29,2990.02 1614.08,3037.81 1614.08,3064 1619.94,3069.86 R22.2@1667.53,3069.86
NetR23_2: R23.2 U2.29 | length 123.9
  Top Layer w10: U2.29@1495.42,2984.81 1495.42,3050.91 1501.28,3056.77 1521.15,3056.77 1528.09,3063.71 1528.09,3081.09 R23.2@1526.32,3082.85
NetR24_2: R24.2 U2.30 | length 103.2
  Top Layer w10: U2.30@1475.74,2984.81 1475.74,3086.32 R24.2@1476.9,3087.48
NetR29_2: R29.2 U3.1 | length 114
  Top Layer w10: v4(687.72,2067.4) 687.72,2101.54 693.58,2107.39 U3.1@718.23,2107.39
  Bottom Layer w10: R29.2@643.63,2074.19 650.42,2067.4 v4(687.72,2067.4)
NetR30_2: R30.2 U3.2 | length 108.1
  Top Layer w10: v4(729.79,2067.4) 729.79,2069.04 739.88,2079.13 U3.2@739.88,2100.5
  Bottom Layer w10: R30.2@692.68,2029.17 722.02,2029.17 727.88,2035.03 727.88,2065.48 v4(729.79,2067.4)
NetR31_2: R31.2 U3.3 | length 79.3
  Top Layer w10: U3.3@758.31,2102.94 760.12,2101.13 760.12,2079.64 761.5,2078.27 v4(761.5,2068.24)
  Bottom Layer w10: v4(761.5,2068.24) 761.5,2038.55 R31.2@771.08,2028.97
NetR32_2: R32.2 U3.4 | length 132.1
  Top Layer w10: U3.4@777.99,2102.94 777.99,2087.05 v4(795.21,2069.83)
  Bottom Layer w10: v4(795.21,2069.83) 797.13,2067.91 844.5,2067.91 850.36,2062.06 R32.2@850.36,2028.6
NetR33_1: R33.1 R35.1 R36.1 | length 142.5
  Top Layer w10: R36.1@498.73,1547.45 502.78,1551.5 R33.1@502.78,1621.33 502.78,1682.57 R35.1@498.73,1686.62
NetR34_2: R34.2 U3.8 | length 198.6
  Top Layer w10: U3.8@779.25,2265.86 U3.8@779.25,2265.86 779.33,2286.79 783.63,2291.1 v1(783.63,2294.34)
  Bottom Layer w10: R34.2@704.79,2408.83 704.79,2338.34 710.65,2332.48 738.26,2332.48 739.03,2333.25 766.64,2333.25 780.62,2319.27 780.62,2305.84
NetR38_2: R38.2 U3.9 | length 222.2
  Top Layer w10: v1(756.75,2309.38) 756.75,2306.13 759.57,2303.32 U3.9@759.57,2265.86
  Bottom Layer w10: R38.2@641.16,2395.9 666.37,2395.9 672.23,2390.05 672.23,2389.86 680.9,2381.2 681.06,2381.2 686.92,2375.34 686.92,2330.94 706.86,2311 755.13,2311 v1(756.75,2309.38)
NetR39_1: R39.1 U3.16 | length 120.1
  Top Layer w10: R39.1@607.48,2092.97 621.18,2106.67 651.15,2106.67 681.41,2136.92 U3.16@709.37,2136.92
nFAULT1: J3.7 R42.1 U2.19 | length 1236.1
  Top Layer w10: U2.19@1560.38,2801.74 1560.46,2801.66 1575.01,2801.66 1593.73,2782.94 1616.44,2782.94 v4(1618.35,2781.03)
  Signal Layer w10: J3.7@1553.51,3689.57 1553.51,3466.02 1564.33,3455.2 1677.66,3455.2 1677.66,2784.06 1674.63,2781.03 v4(1618.35,2781.03)
  Bottom Layer w10: J3.7@1553.51,3689.57 R42.1@1553.51,3775.22
nFAULT2: J3.8 R43.1 U2.7 | length 1599.5
  Top Layer w10: v4(1272.77,2812.06) 1275.48,2812.06 1284.84,2821.42 U2.7@1332.04,2821.42
  Signal Layer w10: v4(1272.77,2812.06) 1275.48,2812.06 1281.65,2818.23 1282.25,2818.23 1298.26,2834.25 1298.26,3014.09 1269.99,3042.36 1269.99,3061.31 1283.39,3074.71 1286.45,3074.71 1292.31,3080.57 1292.31,3083.63 1305.17,3096.49 1305.17,3141.25 1307.59,3143.67 1307.59,3778.23 1313.44,3784.08 1647.66,3784.08 1653.51,3778.23 J3.8@1653.51,3689.57
  Bottom Layer w10: J3.8@1653.51,3689.57 1653.51,3776.26 R43.1@1655.28,3778.02
PFM/SYNC: J3.11 R51.1 U2.34 | length 2400.2
  Top Layer w10: v4(1373.79,3034.02) 1397,3010.82 U2.34@1397,2984.81
  Signal Layer w10: v4(1373.79,3034.02) 1373.79,3008.93 1342.7,2977.84 1342.7,2602.74 1368.93,2576.51 1948.01,2576.51 1953.87,2582.37 1953.87,2998.19 1899.48,3052.58 1899.48,3387.4 1896.36,3390.53 1896.36,3409.47 1899.48,3412.6 1899.48,3635.54 J3.11@1953.51,3689.57
  Bottom Layer w10: R51.1@1919.24,3585.72 1919.24,3655.3 J3.11@1953.51,3689.57
PG1: J3.5 R41.1 U2.21 | length 1106.9
  Top Layer w10: U2.21@1560.38,2841.11 1608.9,2841.11 1613.07,2836.94 v4(1615.77,2836.94)
  Signal Layer w10: J3.5@1353.51,3689.57 1353.51,3149.19 1615.77,2886.93 v4(1615.77,2836.94)
  Bottom Layer w10: J3.5@1353.51,3689.57 1353.51,3777.77 R41.1@1353.76,3778.02
PGND: C1.2 C9.1 C10.1 C11.1 C12.1 C13.1 C14.1 C15.1 C16.1 C17.1 C18.1 C19.1 C20.1 C21.1 C24.1 C25.1 C26.2 C27.2 C29.1 C30.1 C31.1 C32.1 C33.1 C34.1 C35.1 C36.1 C39.2 C40.2 C45.1 C46.1 C47.1 C48.1 C49.1 C50.1 C51.2 C52.2 C57.2 C58.1 C59.1 C60.1 C61.1 C62.1 C63.1 C64.1 C65.1 C66.1 C67.1 C72.1 C73.1 C74.1 C75.1 C76.1 C77.1 C78.1 C79.1 C80.1 C81.1 C82.1 C83.1 C84.1 J2.2 J3.1 J3.4 J4.2 J5.2 J5.3 J5.4 J5.5 J6.2 J6.3 J6.4 J6.5 L2.2 NT3.1 PGND1.1 R10.2 R20.2 R50.2 R51.2 R54.1 R57.1 R58.1 R61.2 RT1.1 RT2.1 U1.6 U2.13 U2.37 U3.6 | length 148
  Top Layer w10: U2.37@1456.05,2880.48 U2.37@1446.21,2870.63 1446.21,2925.86 1456.05,2935.7 NT3.1@1456.05,2946.02
  Top Layer w12: v4@1435.83,2702.06 1435.83,2755.92 U2.13@1436.37,2756.46
  other v1: 2208.58,207.29 2661.16,225.12 2754.31,227.43 2845.14,227.82 2484.3,234.48 2315,235.57 2404.1,235.57 3616.52,496.69 3616.52,564.45 3616.52,631.76 2896.52,648.73 2402.57,711.5 2342.64,714.1 2337.85,769.99 2404.43,770.33 2473.21,769.84 1743.77,1073.69 1695.34,1075.39 1403.36,1076.76 1625.87,1077.34 2422.15,1076.58 2585.02,1077.06 672.26,1078.23 910.32,1078.45 980.68,1077.77 1035.63,1078.45 1106.04,1078.45 1153.92,1077.77 1220.66,1078.45 1268.51,1078.45 1347.08,1078.45 1516.53,1078.29 1576.35,1077.87 2290.12,1077.77 551.21,1078.69 1464.51,1078.68 2475.98,1079.06 2832.87,1079.06 2181.08,1079.87 2236.33,1079.87 498.66,1081.18 614.82,1081.39 796.25,1081.39 2535.8,1081.24 2660.1,1081.24 2769.47,1081.24 2710.52,1082.35 735.14,1082.9 1824.7,1083.28 1880.51,1082.86 1944.34,1084.05 1153.92,1139.54 787.73,1140.93 1268.51,1142.41 502.5,1142.97 551.21,1142.97 618.82,1142.97 667.89,1142.97 738.77,1142.97 2422.41,1142.81 2539.86,1142.59 980.68,1143.86 1035.63,1144.13 1219.14,1143.74 1347.08,1143.86 2590.4,1143.97 2828.05,1144.13 1950.19,1145.81 2111.48,1146.08 2348.36,1145.54 2068.98,1148.22 1994.19,1149.19 2185.04,1149.28 2237.65,1150.15 3086.29,1261.25 3086.29,1380 3087.47,1498.79 1546.9,1684.49 1747.12,1684.49 1498.97,1740 1640,1769.34 1546.9,1813.86 1747.12,1813.86 1623.46,1860.82 1509.61,1884.31 1543.46,1960 1500.95,1997.97 1491.49,2057.18 2537.39,2084.83 2460.92,2086.44 1296.15,2087.3 2404.77,2090.27 1423.15,2091.37 1336.67,2093.88 2326.15,2094.64 1195.41,2102.21 1111.49,2112.13 1168.76,2112.13 2579.36,2114.15 2498.37,2114.81 2278.75,2115.81 1339.09,2120.17 2194.27,2119.61 2456.32,2119.51 1377.15,2120.62 1247.27,2121.72 1893.1,2127.44 1923.49,2126.75 2534.4,2137 1958.23,2142.52 2011.43,2142.71 2097.01,2143.47 2057.82,2145.36 748.61,2145.63 773.36,2145.63 1209.16,2148.18 1129.95,2148.91 1292.68,2152.48 813.33,2159.05 1372.34,2159.35 2455.41,2158.65 1041.51,2160.28 2576.82,2159.69 863.11,2162 911.32,2162.39 957.84,2163.02 2281.86,2167.19 2193.58,2167.84 2011.52,2183.11 1963.49,2184.13 1893.1,2185.37 1923.49,2185.37 2102.11,2185.41 2057.82,2186.44 858.93,2204.26 1040.14,2204.43 1127.74,2203.58 815.36,2206.48 957.89,2205.72 909.37,2207.02 776.32,2209.06 746.24,2209.63 2015.01,2403.57 2090.28,2403.57 946.06,2419.96 853.45,2420.81 2080.73,2487.63 2136.4,2488.47 1972.36,2489.6 2020.13,2489.6 839.3,2503.9 868,2504.88 931.05,2511.5 983.67,2510.96 749.87,2528.76 2110.87,2576.07 2020.23,2577 711.15,2585.52 1531.24,2622.24 1751.62,2647.8 711.15,2709.42 1982.23,3585.72
  other v2: 525,60 702.8,60.45 858.52,60.45 3450,60 1000,65 1155,65 1300,65 1454.17,65 3145,70 3295,70 2980,73.81 1595,75 1751.17,75 1959.34,75 2192.98,100 2315,110.01 2404.1,110.01 2484.3,110.01 2660,110.01 2753.86,110.01 2842.04,110.01 612.16,119.24 1894.8,162.53 559.97,165.43 2315,170 2404.1,170 2484.3,170 2660,170 2753.86,170 2842.04,170 445.35,271.3 3557.94,343.33 566.29,350 1843.27,350 3876.96,350.53 350.53,360 3099.01,363.18 3250,391.68 200,406.07 2009.19,410.98 3871.33,423.99 3444.88,436.25 3743.74,446.76 3847.67,452.47 3129.92,496.03 73.81,507.23 566.29,525 3257.87,597.67 3125,616.5 75,650 2022.23,656.03 1858.51,660.88 275,675 425,675 566.29,675 3257.87,748.84 3072.47,752.19 75,800 3050,839.53 75,945 3049.45,965.13 3848.67,975 3851.29,1050 75,1100 3851.29,1145.54 3862.62,1225 75,1249.72 3860,1342.86 73.81,1399.45 3860,1453.44 73.81,1547.32 3860,1555.52 3860,1648.32 73.81,1700.72 350,1721.3 200,1727.87 3860,1749.54 225,1807.33 174.8,1839.06 3851.29,1850 73.81,1851.63 350,1851.63 163.26,1900 300,1900 1472.63,1945.8 3851.29,1947.22 174.8,1976.49 73.81,2005 3850,2050 300,2062.06 183.03,2116.9 3851.29,2151.93 75,2154.79 3151.25,2200 3250,2200 3005.33,2241.38 75,2306.4 3000,2395 75,2452.34 205.04,2458.52 348.16,2462.23 3000,2545.02 200,2575 337.73,2575 73.81,2594.52 1834.71,2614.22 1919.24,2617.71 3005,2695 1839.03,2718.57 1912.15,2718.57 73.81,2750 475.36,2769.93 595.27,2805.1 731.15,2840.29 929.2,2840.29 3000,2840 1829.83,2867.84 1876.7,2880.48 1925.3,2893.27 70,2900 1061.6,2901.15 1111.49,2954.38 1926.74,2978.51 2995,2994.21 748.25,3018.38 1111.49,3018.38 400,3023.54 961.06,3027.67 70,3055 1926.74,3074.71 1111.49,3133.14 1926.74,3141.25 2995,3142.82 746.24,3191.53 1111.49,3201.4 75,3206.46 400,3206.46 1928.79,3276.08 1129.15,3276.59 2995,3289.68 1135.6,3309.9 75,3348.76 748.25,3380 1138.7,3380 1216.16,3400 1281.65,3400 1384.86,3400 1435.83,3400 1521.15,3400 1640.35,3400 1708.82,3400 1774.4,3400 1817.45,3400 1919.24,3400 2006.52,3400 2995,3450 444.37,3455.2 70,3500 746.24,3550 2994.48,3589.48 475.36,3625 70,3647.71 818.73,3689.57 2971.22,3754.09 70,3800 2863.98,3867.62 145.88,3875 444.37,3875 655,3875 800.44,3875 959.27,3875 1095.99,3875 1253.51,3875 1408.21,3875 1703.5,3875 1847.68,3875 1992.94,3875 2147.92,3875 2311.46,3875 2449.59,3875 2610.99,3875
  other v3: 2473.47,711.9 861.18,1076.76 2348.36,1076.76 2115.89,1077.77 2064.8,1079.87 1994.19,1082.43 1110.22,1140.59 913.1,1144.13 2712.85,1144.37 2774.92,1143.97 1468.45,1145.02 1503.73,1145.11 1590.02,1145.02 1623.03,1145.02 2306.19,1145.11 2470.23,1145.02 1397.84,1146.08 1707.21,1146.3 1741.78,1146.3 1831.4,1146.18 1864.88,1146.18 2656.02,1146.3 863.05,1148.34
  other v4: 3498.87,1652.8 3500.04,1697.86 3500.04,1776.7 3500.04,1825 3500.04,1900 3500.04,1950 1440.01,2610.23 1367.98,2612.48 1437.41,2702.06
  other v5: 1907.79,2159.83 1984.68,2168.69 2081.02,2168.69 763.11,2174.32 840,2183.18 936.34,2183.18 1423.57,2815.52 1468.85,2815.52 1391.09,2848 1423.57,2848 1468.85,2848 1501.33,2848 1391.09,2893.27 1423.57,2893.27 1468.85,2893.27 1501.33,2893.27 1423.57,2925.75 1468.85,2925.75
  other v6: 275,2300 2775,2300 275,2800 2775,2800
SYNCOUT: J3.9 R28.2 U2.33 | length 1904.3
  Top Layer w10: v4(1397.23,3051.82) 1399.14,3049.91 1399.14,3033.95 1416.68,3016.41 U2.33@1416.68,2984.81
  Signal Layer w10: v4(1397.23,3051.82) 1397.23,2999.43 1367.67,2969.87 1367.67,2683.56 1383.23,2668 1737.57,2668 1737.57,3634.86 1744.8,3642.09 1744.8,3680.86 J3.9@1753.51,3689.57
  Bottom Layer w10: R28.2@1384.43,3090.75 1384.43,3064.62 v4(1397.23,3051.82)
TEMPSENSE1: J3.12 R65.2 RT1.2 | length 4104.3
  Top Layer w10: RT1.2@2174.58,2088.64 2179.9,2088.64 2200.65,2067.89 2271.24,2067.89 v7(2290.65,2087.3)
  GND (Mid4) w10: J3.12@2053.51,3689.57 2168.94,3805 2820,3805 2905,3720 2905,1817.86 2894.14,1807 2369.68,1807 2290.65,1886.03 v7(2290.65,2087.3) v7@2290.65,2091.09
  Bottom Layer w10: R65.2@1984.15,3477.23 2047.66,3477.23 2053.51,3483.09 J3.12@2053.51,3689.57
TEMPSENSE2: J3.6 R64.2 RT2.2 | length 4934.8
  Top Layer w10: RT2.2@1025.05,2108.93 1025.05,2082.28 1030.91,2076.43 v7(1125.18,2076.43)
  GND (Mid4) w10: v7(1125.18,2076.43) 1125.18,1886.34 1061.71,1822.86 346.43,1822.86 307.35,1861.93 201.58,1861.93 195.72,1867.79 195.72,1925.9 197.67,1927.85 197.67,2078.47 183.19,2092.95 174.63,2092.95 160.16,2107.43 160.16,2234 145,2249.16 145,2357.52 173.18,2385.69 173.18,2703.56 177.75,2708.13 177.75,2716.41 147.13,2747.03 147.13,3824.71 162.42,3840 1361.92,3840 1453.51,3748.41 J3.6@1453.51,3689.57
  Bottom Layer w10: J3.6@1453.51,3689.57 1453.51,3573.53 1459.37,3567.67 1554.01,3567.67 R64.2@1555.32,3568.98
